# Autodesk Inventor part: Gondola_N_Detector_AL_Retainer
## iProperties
Shininess: 64.0
Length Units: 11272
Angle Units: 11279
Time Units: 11290
Mass Units: 11286
Length Display Precision: 3
Angle Display Precision: 2
Compacted: True
Part Number: Gondola_N_Detector_AL_Retainer
Document SubType Name: Modeling
Created: 2004-12
Designer: John Blackburn
Manufacturer: Standard
Standards Organization: Custom
Density: 0.0
Volumn: 0.0
Area: 0.0
PropertySet Name: Model Information
Control State: 0
Master: False
Checked Out: False
Author: John Blackburn
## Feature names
1. Extrusion1
2. Extrusion2
